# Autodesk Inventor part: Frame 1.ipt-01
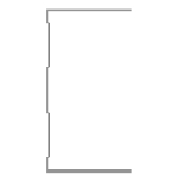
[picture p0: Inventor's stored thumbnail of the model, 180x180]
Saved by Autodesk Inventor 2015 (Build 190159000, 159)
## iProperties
Created: 2015-04
Part Number: Frame 1.ipt-01
Material: Aluminum 6061
Description: Kévin Novo
Document SubType Name: Modeling
Standard: Kevin
Designer: suporte
Standards Organization: Kevin
Language: en-US
Size Designation: (Unnamed 1)
Categories: <MemberInstance><Categories><Category DisplayName="Structural Shapes" InternalName="089c4875-fa83-4c05-b084-43b9cc11f5ed" Mnemonic="GRDR"><CategoryParameter Dis
Density: 2.7 g/cm^3
Appearance: Aluminum - Flat
IsCustomPart: 1
G_L: 1086,186 mm
G_W: 50,000 mm
G_H: 75,000 mm
+BC625CA7-C02F-465B-8547-A92C4635F835+CUTDETAIL1: Cut
+90C232A2-F113-4F90-9BE8-95EAE997F2A7+CUTDETAIL2: Cut
_CCFamilyMember: 1
_CCFamilyDisplayName: Kévin - Kévin Novo
_FrameMemberDoc: Frame Member File
_Version: 15.0.0
_GetPNFromCC: 1
Author: suporte
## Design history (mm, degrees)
node "Start Plane"
node "End Plane"
sketch "Sketch"
  geometry: L1 (24.7, 37.5)-(24.7, 36.9); L2 (24.7, 36.9)-(-24.7, 36.9); L3 (-24.7, -36.9)-(24.7, -36.9); L4 (24.7, -36.9)-(24.7, -37.5); L5 (24.7, -37.5)-(-25.3, -37.5); L6 (-25.3, 37.5)-(24.7, 37.5); L7 (-24.7, 36.9)-(-24.7, 31.9); L8 (-24.7, 31.9)-(-23.3, 30.5); L9 (-23.3, 30.5)-(-23.3, 10.934); L10 (-23.3, 10.934)-(-24.7, 9.534); L11 (-24.7, 9.534)-(-24.7, -9.534); L12 (-24.7, -9.534)-(-23.3, -10.934); L13 (-23.3, -10.934)-(-23.3, -30.5); L14 (-23.3, -30.5)-(-24.7, -31.9); L15 (-24.7, -31.9)-(-24.7, -36.9); L16 (-25.3, -37.5)-(-25.3, -31.651); L17 (-25.3, -31.651)-(-23.9, -30.251); L18 (-23.9, -30.251)-(-23.9, -11.183); L19 (-23.9, -11.183)-(-25.3, -9.783); L20 (-25.3, -9.783)-(-25.3, 9.783); L21 (-25.3, 9.783)-(-23.9, 11.183); L22 (-23.9, 11.183)-(-23.9, 30.251); L23 (-23.9, 30.251)-(-25.3, 31.651); L24 (-25.3, 31.651)-(-25.3, 37.5); L25 (-25.3, 0)-(30.37, 0); 3 further points
  constraints: 50 end point, 10 point on line, 9 parallel, 5 perpendicular, 4 equal length, 3 midpoint, 3 vertical, 2 vertical alignment, 1 collinear, 1 horizontal, 1 horizontal alignment
  dimensions: "d3" = 0.6 distance of L1.start L1.end (= d6); "d5" = 75 distance between parallel lines of L5 L6; "d6" = 0.6 distance between parallel lines of L24 L7 (= d8); "d7" = 0.6 distance between parallel lines of L8 L23 (= d8); "d8" = 0.6 distance between parallel lines of L22 L9 (= d12); "Espessura" = 0.6 distance between parallel lines of L17 L14; "d10" = 0.6 distance between parallel lines of L13 L18 (= Espessura); "d11" = 0.6 distance between parallel lines of L12 L19 (= Espessura); "d12" = 0.6 distance between parallel lines of L21 L10 (= d11); "d13" = 5 distance of L2.end L7.end; "d15" = 135 deg angle of L9 L8; "d16" = 2 distance between parallel lines of L24 L9; "d17" = 50 distance of L6.start L1.start
extrude "Body" join sketch "Sketch" stored distance "d24" = 0.13; taper "d25" = 0 deg
node "Driven Length"
  sketch "Sketch10"
    geometry: L1 (0, 0)-(10, 0) reference
    constraints: 2 end point, 1 horizontal
  workplane "Work Plane7"
  sketch "Sketch11"
    geometry: L1 (-2, 12.5)-(12, 12.5) reference; L2 (-2, 1098.686)-(12, 1098.686) reference
    dimensions: "d27" = 1086.1863 distance between parallel lines of L1 L2 (derived)
workplane "Work Plane8"
split "Split1"
workplane "Work Plane9"
split "Split2"
body "Solid1"
other parameters: "tamanho" = 1018.55826, "G_OFFSET_START" = -12.5 [user parameter; used in 1 equation term], "G_OFFSET_END" = 80.12804 [user parameter; used in 1 equation term], "d22" = 12.5 (= -G_OFFSET_START), "d23" = 1098.6863 (= tamanho + G_OFFSET_END), "G_L" = 1086.1863 (= d27) [user parameter], "d34" = 90 deg
